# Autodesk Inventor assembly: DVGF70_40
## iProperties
Created: 2010-04
Part Number: DVGF70_40
Document SubType Name: Assembly
Designer: TB
Mass: 1552.23 g
Surface Area: 2160.87 cm^2
Volume: 1552.23 cm^3
Density: 1 g/cm^3
Description: KM DVGF 70/40 - 100 mm
Slaglengde: 100.000 mm
Author: TB
